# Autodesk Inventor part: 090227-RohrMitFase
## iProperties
Created: 2009-02
Part Number: 090227-RohrMitFase
Document SubType Name: Modeling
Designer: mp
Density: 1 g/cm^3
Author: mp
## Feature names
1. Extrusion1
2. Trennen1
3. Trennen2
